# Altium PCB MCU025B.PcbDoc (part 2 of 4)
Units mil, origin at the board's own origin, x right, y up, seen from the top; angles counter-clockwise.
Board outline 2300 x 6150 mil, 6 copper layers (Top Signal, GND, Middle Signal, PWR, GND2, Bottom Signal), stack 61.64 mil thick; 237 components, 197 nets, 910 pads, 404 vias.
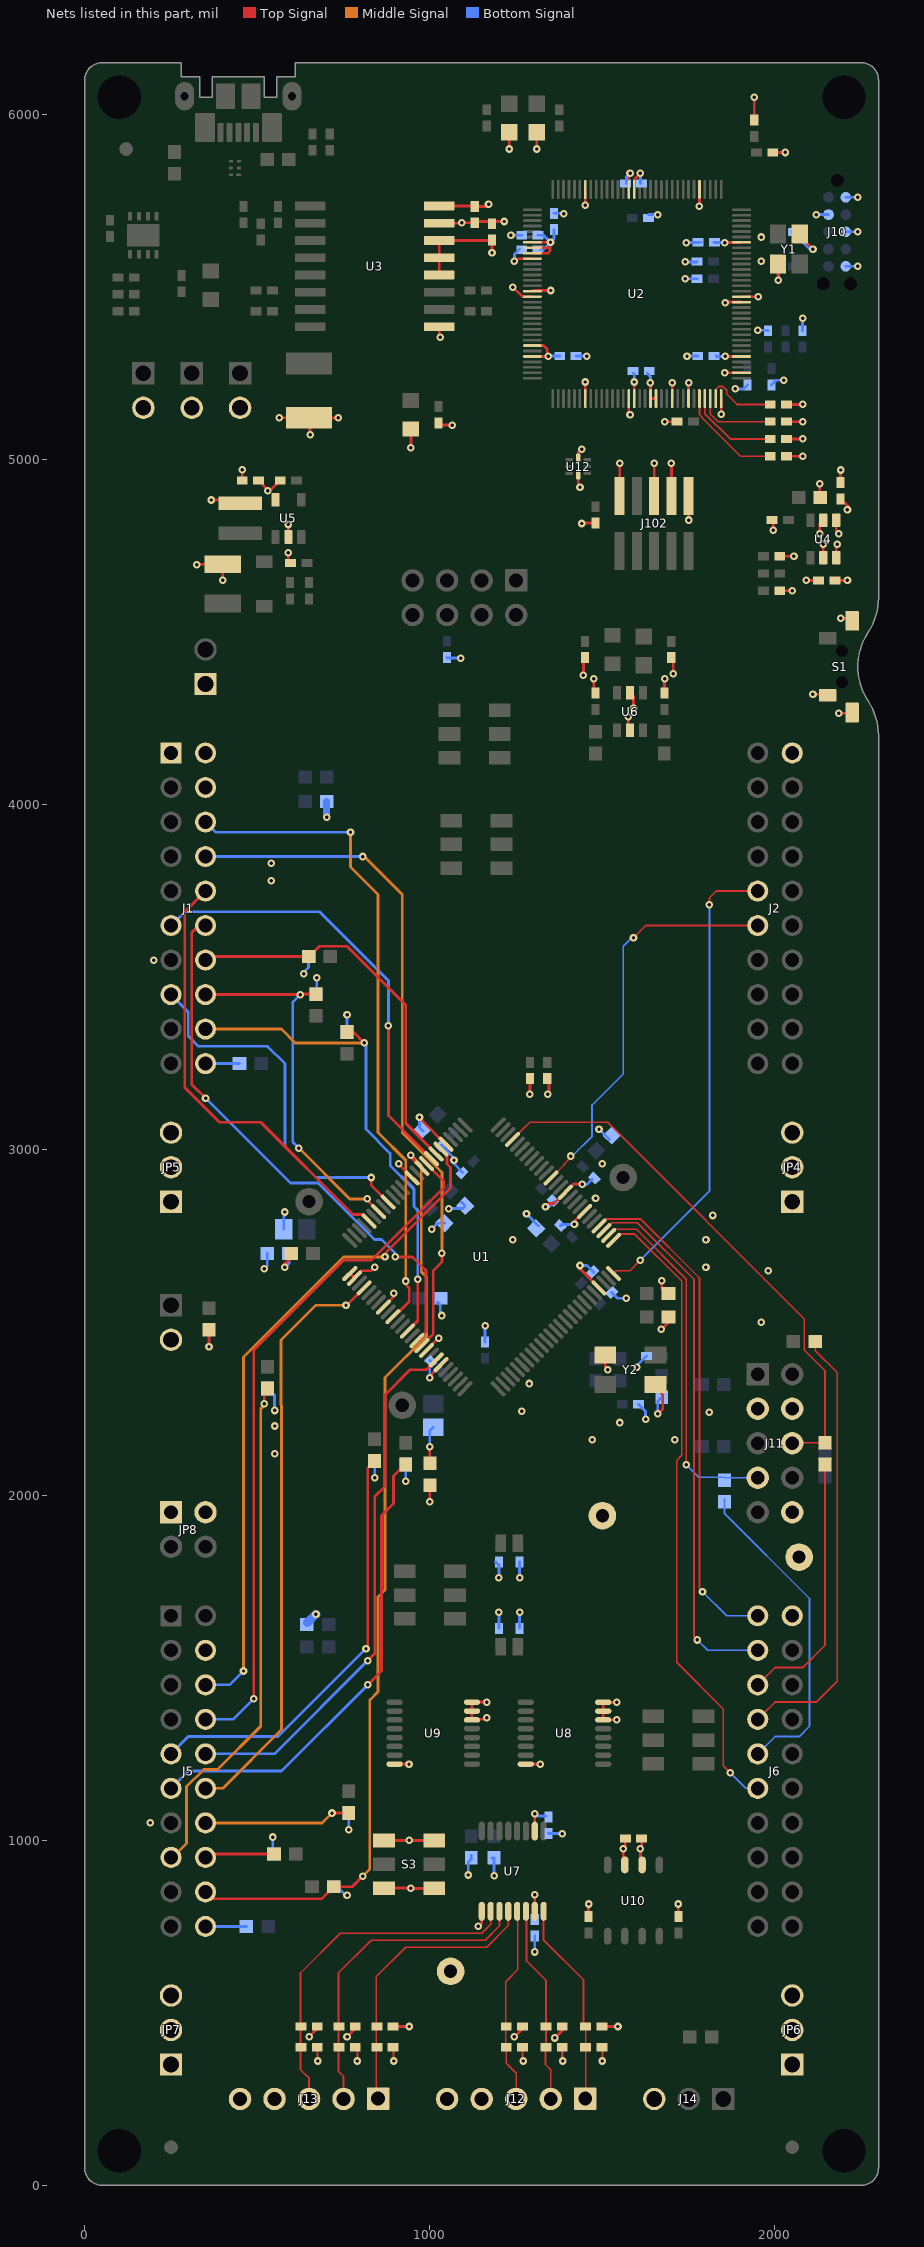
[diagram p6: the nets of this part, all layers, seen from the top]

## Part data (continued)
C3: library part CMP-0006493-2, "CAP, CERM, 820 pF, 50 V, +/- 5%, C0G/NP0, 0402", Cap_Case=0402, Manufacturer=MuRata, Supplier Part Number 1=490-3242-1-ND, TempCo=C0G/NP0, Tolerance_%=5%, Value1=Unknown, Value2=50V, ValueDisplayed=820pF
C4: library part CMP-0009190-2, "CAP, CERM, 10 uF, 25 V, +/- 10%, X7R, 1210", Cap_Case=1210, Manufacturer=MuRata, Supplier Part Number 1=490-1867-1-ND, TempCo=X7R, Tolerance_%=10%, Value1=Unknown, Value2=25V, ValueDisplayed=10uF
C5: library part CMP-0006552-2, "CAP, CERM, 4.7 uF, 6.3 V, +/- 20%, X5R, 0402", Cap_Case=0402, Manufacturer=MuRata, Supplier Part Number 1=490-5915-1-ND, TempCo=X5R, Tolerance_%=20%, Value1=Unknown, Value2=6.3V, ValueDisplayed=4.7uF
C7 C8 C50 C51 C52 C53 C58: library part CMP-0006658-2, "CAP, CERM, 0.01 uF, 25 V, +/- 10%, X7R, 0402", Cap_Case=0402, Manufacturer=MuRata, Supplier Part Number 1=490-1312-1-ND, TempCo=X7R, Tolerance_%=10%, Value1=Unknown, Value2=25V, ValueDisplayed=0.01uF
C9 C10 C19 C20: library part CMP-0007318-5, "CAP, CERM, 10 uF, 10 V, +/- 20%, X5R, 0603", Cap_Case=0603, Manufacturer=MuRata, TempCo=X5R, Tolerance_%=20%, Value1=Unknown, Value2=10V, ValueDisplayed=10uF
C15 C16 C17 C18 C35 C36: library part CMP-0007323-5, "CAP, CERM, 2.2 uF, 10 V, +/- 10%, X5R, 0603", Cap_Case=0603, Manufacturer=MuRata, Supplier Part Number 1=490-1545-1-ND, TempCo=X5R, Tolerance_%=10%, Value1=Unknown, Value2=10V, ValueDisplayed=2.2uF
C26 C27 C28 C29 C30 C31 C32 C33 C34: library part CMP-0007209-4, "CAP, CERM, 330 pF, 50 V, +/- 5%, C0G/NP0, 0603", Cap_Case=0603, Manufacturer=MuRata, Supplier Part Number 1=490-1439-1-ND, TempCo=C0G/NP0, Tolerance_%=5%, Value1=Unknown, Value2=50V, ValueDisplayed=330pF
C38 C39 C102: library part CMP-0006420-2, "CAP, CERM, 15 pF, 50 V, +/- 5%, C0G/NP0, 0402", Cap_Case=0402, Manufacturer=MuRata, Supplier Part Number 1=81-GRM1555C1H150JA1D, TempCo=C0G/NP0, Tolerance_%=5%, Value1=Unknown, Value2=50V, ValueDisplayed=15pF
C43 C44 C45 C46 C47 C48: library part CMP-0006673-2, "CAP, CERM, 1000 pF, 50 V, +/- 10%, X7R, 0402", Cap_Case=0402, Manufacturer=MuRata, Supplier Part Number 1=490-1303-1-ND, TempCo=X7R, Tolerance_%=10%, Value1=Unknown, Value2=50V, ValueDisplayed=1000pF
C54 C55 C60 C66: library part CMP-0006623-2, "CAP, CERM, 0.1 uF, 6.3 V, +/- 10%, X7R, 0402", Cap_Case=0402, Manufacturer=MuRata, Supplier Part Number 1=GRM155R70J104KA01D-ND, TempCo=X7R, Tolerance_%=10%, Value1=Unknown, Value2=6.3V, ValueDisplayed=0.1uF
C56 C57 C61: library part CMP-0006563-2, "CAP, CERM, 1 uF, 10 V, +/- 10%, X5R, 0402", Cap_Case=0402, Manufacturer=MuRata, Supplier Part Number 1=490-3890-1-ND, TempCo=X5R, Tolerance_%=10%, Value1=Unknown, Value2=10V, ValueDisplayed=1uF
C59 C100 C103: library part CMP-0006543-2, "CAP, CERM, 2.2 uF, 6.3 V, +/- 10%, X5R, 0402", Cap_Case=0402, Manufacturer=MuRata, Supplier Part Number 1=81-GRM155R60J225KE5D, TempCo=X5R, Tolerance_%=10%, Value1=Unknown, Value2=6.3V, ValueDisplayed=2.2uF
C62 C63: library part CMP-0006415-2, "CAP, CERM, 12 pF, 50 V, +/- 5%, C0G/NP0, 0402", Cap_Case=0402, Manufacturer=MuRata, Supplier Part Number 1=14T3292, TempCo=C0G/NP0, Tolerance_%=5%, Value1=Unknown, Value2=50V, ValueDisplayed=12pF
C101: library part CMP-0006688-2, "CAP, CERM, 3300 pF, 50 V, +/- 10%, X7R, 0402", Cap_Case=0402, Manufacturer=MuRata, Supplier Part Number 1=490-3248-1-ND, TempCo=X7R, Tolerance_%=10%, Value1=Unknown, Value2=50V, ValueDisplayed=3300pF
C104: library part CMP-0009297-2, "CAP, CERM, 0.01 uF, 1500 V, +/- 10%, X7R, 1812", Cap_Case=1812, Manufacturer=AVX, Supplier Part Number 1=478-4735-1-ND, TempCo=X7R, Tolerance_%=10%, Value1="0.05 ohm", Value2=1500V, ValueDisplayed=0.01uF
"CE Logo1": library part CMP-0074844-1
D1: library part CMP-0028360-1, "Diode, Schottky, 40 V, 1 A, SOD-123", Manufacturer="Diodes Inc.", Supplier Part Number 1=1N5819HW-FDICT-ND, Value1=1A, Value2=0.45V
FID1 FID2 FID3 FID4 FID5 FID6: library part CMP-0077181-1, "Fiducial mark.  There is nothing to buy or mount.", Manufacturer=N/A
J1 J5: library part CMP-0003837-2, "Receptacle, 2.54mm, 10x2, Tin, TH", Alternate Manufacturer="Major League Electronics", Alternate PartNumber=CRD-081413-A-G, Manufacturer=Samtec, Supplier Part Number 1=SAM1204-10-ND
J2 J6: library part CMP-0078266-2, "Receptacle, 2.54mm, 10x2, Tin, TH", Alternate Manufacturer="Major League Electronics", Alternate PartNumber=CRD-081413-A-G, Manufacturer=Samtec, Supplier Part Number 1=SAM1204-10-ND
J10: library part CMP-0075101-1, "Footprint for Tag-Connect TC2050 No-Legs cables", Manufacturer=Tag-Connect
J11: library part CMP-0075410-2, "Header, 100mil, 5x2, Gold, TH", Color=Black, Current_A=6.3A, Manufacturer=Samtec, Supplier Part Number 1=SAM1028-05-ND, Voltage_V=550V
J12 J13: library part CMP-0075411-1, "Header, 100mil, 5x1, Gold, TH", Color=Black, Current_A=6.3A, Manufacturer=Samtec, Supplier Part Number 1=SAM1029-05-ND, Voltage_V=550V
J14 JP4 JP5 JP6 JP7: library part CMP-0054796-1, "Header, 2.54 mm, 3x1, Gold, TH", Manufacturer="Wurth Elektronik", Supplier Part Number 1=732-5316-ND
J15 JP1 JP2 JP3 JP9: library part CMP-0054794-1, "Header, 2.54 mm, 2x1, Gold, TH", Manufacturer="Wurth Elektronik", Supplier Part Number 1=732-5315-ND
J101: library part CMP-0075408-1, "Header, 100mil, 4x2, Gold, TH", Color=Black, Current_A=6.3A, Manufacturer=Samtec, Supplier Part Number 1=SAM1028-04-ND, Voltage_V=550V
J102: library part CMP-0075670-1, "Header (Shrouded), 1.27mm, 5x2, Gold, SMT", Color=Black, Current_A=3.3A, Manufacturer=Samtec, Supplier Part Number 1=SAM8796-ND
JP8: library part CMP-0075404-1, "Header, 100mil, 2x2, Gold, TH", Color=Black, Current_A=6.3A, Manufacturer=Samtec, Supplier Part Number 1=SAM1028-02-ND, Voltage_V=550V
L1: library part CMP-0063754-1, "Inductor, Shielded Drum Core, Ferrite, 3.3 uH, 1.5 A, 0.085 ohm, SMD", Manufacturer="Wurth Elektronik", Supplier Part Number 1=732-2614-1-ND, Value1="0.085 ohm", Value2=1.5A, ValueDisplayed=3.3uH
L2: library part CMP-0003306-1, "Ferrite Bead, 60 ohm @ 100 MHz, 3 A, 0805", Manufacturer="Taiyo Yuden", Supplier Part Number 1=587-1932-1-ND, Value1="0.025 ohm", Value2=3A, ValueDisplayed="60 ohm"
L3: library part CMP-0003363-1, "Ferrite Bead, 220 ohm @ 100 MHz, 2 A, 0805", Manufacturer=MuRata, Supplier Part Number 1=490-1054-1-ND, Value1="0.045 ohm", Value2=2A, ValueDisplayed="220 ohm"
L100 L101: library part CMP-0003183-2, "Ferrite Bead, 100 ohm @ 100 MHz, 0.5 A, 0603", Manufacturer="Wurth Elektronik", Supplier Part Number 1=732-1579-1-ND, Value1="0.15 ohm", Value2=0.5A, ValueDisplayed="100 ohm"
LED0 LED1 LED4: library part CMP-0002951-2, "LED, Red, SMD", Color=Red, Manufacturer="Wurth Elektronik", Power_TotalModule=72mW, Supplier Part Number 1=732-4985-1-ND, Value1=0.072W, Value2=1.9V
LED2 LED3: library part CMP-0002889-1, "LED, Blue, SMD", Color=Blue, Manufacturer=Lite-On, Supplier Part Number 1=160-1579-1-ND, Value1=W, Value2=3.3V
LED5: library part CMP-0002830-2, "LED, Green, SMD", Color=green, Manufacturer=Lite-On, Supplier Part Number 1=160-1423-1-ND, Value1=W, Value2=2.1V
Logo1: library part CMP-0074838-1, "Texas Instrument Corporate Signature"
Logo2: library part CMP-0074769-1
Logo3: library part CMP-0074847-1, "FCC_disclaimer"
Logo4: library part CMP-0861049-2, "INSTASPIN FOC LOGO"
M1 M2 M3 M4 M5 M6 M7 M8 M9: library part CMP-0003761-2, "Shunt, 2.54mm, Gold, Black", Manufacturer="Wurth Elektronik", Supplier Part Number 1=732-2678-ND
MH1 MH2 MH3 MH4: library part CMP-0078424-2, "PCB Mounting Hole, No Pad", Manufacturer=Any, PartNumber=N/A
R1 R2 R103 R104: library part CMP-0026197-2, "RES, 24.3, 1%, 0.063 W, AEC-Q200 Grade 0, 0402", Manufacturer=Vishay-Dale, Power_W=63mW, Supplier Part Number 1=541-24.3LCT-ND, TempCo="100 ppm/C", Tolerance_%=1%, Value2=0.063W, Value_Code=24R3, ValueDisplayed=24.3
R3 R29 R30 R105: library part CMP-0026962-3, "RES, 680, 5%, 0.063 W, AEC-Q200 Grade 0, 0402", Manufacturer=Vishay-Dale, Power_W=63mW, Supplier Part Number 1=541-680JCT-ND, TempCo="200 ppm/C", Tolerance_%=5%, Value2=0.063W, Value_Code=680R, ValueDisplayed=680
R4 R10 R32 R40 R41: library part CMP-0026890-5, "RES, 2.2 k, 5%, 0.063 W, AEC-Q200 Grade 0, 0402", Manufacturer=Vishay-Dale, Power_W=63mW, Supplier Part Number 1=541-2.2KJCT-ND, TempCo="200 ppm/C", Tolerance_%=5%, Value2=0.063W, Value_Code=2k20, ValueDisplayed=2.2k
R5: library part CMP-0026822-3, "RES, 0, 5%, 0.063 W, AEC-Q200 Grade 0, 0402", Manufacturer=Vishay-Dale, Power_W=63mW, Supplier Part Number 1=541-0.0JCT-ND, TempCo="200 ppm/C", Tolerance_%=5%, Value2=0.063W, Value_Code=0000, ValueDisplayed=0
R6 R42: library part CMP-0025769-4, "RES, 2.2 k, 5%, 0.1 W, AEC-Q200 Grade 0, 0603", Manufacturer=Vishay-Dale, Power_W=100mW, Supplier Part Number 1=541-2.2KGCT-ND, TempCo="200 ppm/C", Tolerance_%=5%, Value2=0.1W, Value_Code=2k20, ValueDisplayed=2.2k
R7: library part CMP-0026730-1, "RES, 30.1 k, 1%, 0.063 W, 0402", Manufacturer="Yageo America", Power_W=63mW, Supplier Part Number 1=311-30.1KLRCT-ND, TempCo="100 ppm/C", Tolerance_%=1%, Value2=0.063W, Value_Code=30k1, ValueDisplayed=30.1k
R8 R9 R65 R67: library part CMP-0026825-5, "RES, 10 k, 5%, 0.063 W, AEC-Q200 Grade 0, 0402", Manufacturer=Vishay-Dale, Power_W=63mW, Supplier Part Number 1=541-10KJCT-ND, TempCo="200 ppm/C", Tolerance_%=5%, Value2=0.063W, Value_Code=10k0, ValueDisplayed=10k
R11 R12 R13 R14 R15 R16 R17 R18 R19 R20 R21 R22 R23 R24 R25 R26 R27 R28 R31 R35 R38 R39 R43 R44 R45 R46 R47 R71 R72: library part CMP-0025697-4, "RES, 0, 5%, 0.1 W, AEC-Q200 Grade 0, 0603", Manufacturer=Vishay-Dale, Power_W=100mW, Supplier Part Number 1=541-0.0GCT-ND, TempCo="200 ppm/C", Tolerance_%=5%, Value2=0.1W, Value_Code=0000, ValueDisplayed=0
R33 R34: library part CMP-0026949-3, "RES, 56 k, 5%, 0.063 W, AEC-Q200 Grade 0, 0402", Manufacturer=Vishay-Dale, Power_W=63mW, Supplier Part Number 1=541-56KJCT-ND, TempCo="200 ppm/C", Tolerance_%=5%, Value2=0.063W, Value_Code=56k0, ValueDisplayed=56k
R36 R37: library part CMP-0026826-2, "RES, 10 M, 5%, 0.063 W, AEC-Q200 Grade 0, 0402", Manufacturer=Vishay-Dale, Power_W=63mW, Supplier Part Number 1=541-10MJCT-ND, TempCo="200 ppm/C", Tolerance_%=5%, Value2=0.063W, Value_Code=10M0, ValueDisplayed=10M
R48 R49 R50 R51 R52 R53: library part CMP-0026071-3, "RES, 1.00 k, 1%, 0.063 W, AEC-Q200 Grade 0, 0402", Manufacturer=Vishay-Dale, Power_W=63mW, Supplier Part Number 1=541-1.00KLCT-ND, TempCo="100 ppm/C", Tolerance_%=1%, Value2=0.063W, Value_Code=1k00, ValueDisplayed=1.00k
R54 R56: library part CMP-0025958-3, "RES, 10.0 k, 1%, 0.063 W, AEC-Q200 Grade 0, 0402", Manufacturer=Vishay-Dale, Power_W=63mW, Supplier Part Number 1=541-10.0KLCT-ND, TempCo="100 ppm/C", Tolerance_%=1%, Value2=0.063W, Value_Code=10k0, ValueDisplayed=10.0k
R55: library part CMP-0022769-3, "RES, 120, 1%, 0.1 W, 0603", Manufacturer="Yageo America", Power_W=100mW, Supplier Part Number 1=311-120HRCT-ND, TempCo="200 ppm/C", Tolerance_%=1%, Value2=0.1W, Value_Code=120R, ValueDisplayed=120
R57: library part CMP-0026918-5, "RES, 3.3 k, 5%, 0.063 W, AEC-Q200 Grade 0, 0402", Manufacturer=Vishay-Dale, Power_W=63mW, Supplier Part Number 1=541-3.3KJCT-ND, TempCo="200 ppm/C", Tolerance_%=5%, Value2=0.063W, Value_Code=3k30, ValueDisplayed=3.3k
R58 R59 R60 R61: library part CMP-0026852-3, "RES, 1.0 k, 5%, 0.063 W, AEC-Q200 Grade 0, 0402", Manufacturer=Vishay-Dale, Power_W=63mW, Supplier Part Number 1=541-1.0KJCT-ND, TempCo="200 ppm/C", Tolerance_%=5%, Value2=0.063W, Value_Code=1k00, ValueDisplayed=1.0k
R62 R66: library part CMP-0026824-3, "RES, 100, 5%, 0.063 W, AEC-Q200 Grade 0, 0402", Manufacturer=Vishay-Dale, Power_W=63mW, Supplier Part Number 1=541-100JCT-ND, TempCo="200 ppm/C", Tolerance_%=5%, Value2=0.063W, Value_Code=100R, ValueDisplayed=100
R63 R64: library part CMP-0026699-1, "RES, 470, 1%, 0.1 W, AEC-Q200 Grade 0, 0402", Manufacturer=Panasonic, Power_W=100mW, Supplier Part Number 1=P470LCT-ND, TempCo="100 ppm/C", Tolerance_%=1%, Value2=0.1W, Value_Code=470R, ValueDisplayed=470
R68: library part CMP-0026413-2, "RES, 4.87 k, 1%, 0.063 W, AEC-Q200 Grade 0, 0402", Manufacturer=Vishay-Dale, Power_W=63mW, Supplier Part Number 1=541-4.87KLCT-ND, TempCo="100 ppm/C", Tolerance_%=1%, Value2=0.063W, Value_Code=4k87, ValueDisplayed=4.87k
R70: library part CMP-0026946-3, "RES, 51, 5%, 0.063 W, AEC-Q200 Grade 0, 0402", Manufacturer=Vishay-Dale, Power_W=63mW, Supplier Part Number 1=541-51JCT-ND, TempCo="200 ppm/C", Tolerance_%=5%, Value2=0.063W, Value_Code=51R0, ValueDisplayed=51
R100: library part CMP-0026100-2, "RES, 1.00 M, 1%, 0.063 W, AEC-Q200 Grade 0, 0402", Manufacturer=Vishay-Dale, Power_W=63mW, Supplier Part Number 1=541-1.00MLCT-ND, TempCo="100 ppm/C", Tolerance_%=1%, Value2=0.063W, Value_Code=1M00, ValueDisplayed=1.00M
R101: library part CMP-0088102-2, "RES Thick Film SMD 51kO 1% 1/16W 0402 100ppm/K", Manufacturer=Vishay, Power_W=63mW, Tolerance_%=1%, ValueDisplayed=51k
R102: library part CMP-0078244-2, "RES, 30.0 k, 1%, 0.063 W, AEC-Q200 Grade 0, 0402", Manufacturer=Vishay-Dale, Power_W=63mW, Supplier Part Number 1=541-30.0KLCT-ND, TempCo="100 ppm/C", Tolerance_%=1%, Value2=0.063W, Value_Code=30k0, ValueDisplayed=30.0k
S1: library part CMP-0002328-1, "Switch, SPST, 0.05 A, 12 VDC, SMD", CurrentRating_mA=50A, Manufacturer=Diptronics
S2: library part CMP-0002230-1, "Switch, SPST, 2 Pos, 25mA, 24VDC, SMD", CurrentRating_mA=25A, Manufacturer="CTS Electrocomponents", Supplier Part Number 1=CT2182LPST-ND
S3: library part CMP-0002233-1, "Switch, Dual SPDT,  2 Pos, 0.1A, 6VDC, SMD", CurrentRating_mA=100A, Manufacturer="Copal Electronics", Supplier Part Number 1=CASD20JCT-ND
S4 S6 S8 S9: library part CMP-0002123-2, "SLIDE SWITCH DPDT  .1A, SMT", CurrentRating_mA=100A, Manufacturer="Copal Electronics", Supplier Part Number 1=CAS220JCT-ND
TP1 TP2 TP3 TP4 TP5 TP6: library part CMP-0078143-2, "TEST POINT.  No entry in BOM.", Manufacturer=N/A
U1: library part CMP-0078352-1, "Piccolo Microcontroller, PZ0100A (LQFP-100)", Alternate Manufacturer="Texas Instruments"
U2: library part CMP-0077953-1, "MSP432E401YTPDT, PDT0128A (TQFP-128)", Alternate Manufacturer="Texas Instruments", Alternate PartNumber=MSP432E401YTPDTR
U3: library part CMP-0074604-2, "Full/Low Speed 2.5 kV USB Digital Isolator, SOIC-16", Manufacturer="Analog Devices", Supplier Part Number 1=ADUM3160BRWZ-ND
U4: library part CMP-0067340-2, "High-Accuracy, Fixed-Threshold OV/UV Monitor, DDC0006A (SOT-23-T-6)", Alternate Manufacturer="Texas Instruments", Alternate PartNumber=TPS3702CX33DDCT
U5: library part CMP-0066119-1, "SIMPLE SWITCHER 2.7V to 5.5V, 2.1A Step-Up Regulator in SOT-23, DBV0005A (SOT-23-5)", Alternate Manufacturer="Texas Instruments", Alternate PartNumber=LMR62421XMFE/NOPB
U6: library part CMP-0051789-2, "Dual Buffer/Driver with Open-Drain Output, DBV0006A, LARGE T&R", F @ Nom Voltage(Max)(Mhz)=150, Generic Part Number=SN74LVC2G07, ICC @ Nom Voltage(Max)(mA)=0.01, Manufacturer="Texas Instruments", Operating Temperature Range(C)="-40 to 125", Rating=Catalog, tpd @ Nom Voltage(Max)(ns)=8.6,4.4,3.7,2.9, Voltage(Nom)(V)=1.8,2.5,3.3,5
U7: library part CMP-0067443-1, "6-Bit Bidirectional Voltage-Level Translator with Auto Direction Sensing and +/-15-kV ESD Protect, PW0016A (TSSOP-16)", Alternate Manufacturer="Texas Instruments"
U8 U9: library part CMP-0076549-1, "TRIPLE 2-CHANNEL ANALOG MULTIPLEXER/DEMULTIPLEXER, PW0016A (TSSOP-16)", Alternate Manufacturer="Texas Instruments"
U10: library part CMP-0033355-1, "3.3V CAN Transceiver with Sleep Mode, 6 mA, -40 to 125 degC, 8-pin SOIC (D), Green (RoHS & no Sb/Br)", Bus Fault Voltage(V)=+/-30, Drivers Per Package=1, Low Power Mode=Sleep, Manufacturer="Texas Instruments", Rating=Catalog, Supply Voltage(s)(V)=3.3
U12: library part CMP-0043125-2, "Low-Capacitance + / - 15 kV ESD Protection Array for High-Speed Data Interfaces, 6 Channels, -40 to +85 degC, 8-pin UQFN (RSE), Green (RoHS & no Sb/Br)", Breakdown Voltage(Min)(V)=6, IO Capacitance(Typ)(pF)=1.6, IO Leakage Current(nA)=1, Manufacturer="Texas Instruments"
U100: library part CMP-0043115-2, "ESD-Protection Array for High-Speed Data Interfaces, 4 Channels, -40 to +85 degC, 6-pin SON (DRY), Green (RoHS & no Sb/Br)", Breakdown Voltage(Min)(V)=6, IO Capacitance(Typ)(pF)=1.6, IO Leakage Current(nA)=1, Manufacturer="Texas Instruments"
U101: library part CMP-0036402-3, "Single Output High PSRR LDO, 1 A, Adjustable 1.2 to 5.5 V Output, 2.7 to 5.5 V Input, 8-pin SON (DRB), -40 to 125 degC, Green (RoHS & no Sb/Br)", Manufacturer="Texas Instruments"
USB101: library part CMP-0055311-1, "Receptacle, USB 2.0, Micro B, 5 Position, R/A, SMT", Color=Black, Current_A=1.8A, Manufacturer=Molex, Supplier Part Number 1=WM11263CT-ND, Voltage_V=30V
Y1: library part CMP-0004635-3, "Crystal, 16 MHz, 8pF, SMD", Frequency_Fixed=16MHz, Frequency Stability=+/-30ppm, Manufacturer=NDK, Supplier Part Number 1=644-1157-1-ND
Y2: library part CMP-0080365-1, "Crystal, 20 MHz, 25 ppm, 18, SMD", Frequency_Fixed=20MHz, Frequency Stability="30 ppm", Frequency Tolerance="25 ppm", Load Capacitance=18, Manufacturer="ECS Inc.", Supplier Part Number 1=XC2693CT-ND
ZZ2: library part CMP-0077236-1
ZZ3: library part CMP-0077237-1
ZZ4: library part CMP-0077238-1

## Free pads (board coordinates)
  round 0 on Mech16 paste+0 mask+0: 1(496.18,5248.19) 1(496.18,5248.19)
  rrect9% 41.73x57.87 on Top Paste: 9(145.2,5650) 9(194.8,5650)

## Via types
v1: diameter 22, hole 10, Top Signal to Bottom Signal, tented both sides, 400 vias
v2: diameter 19.68, hole 7.87, Top Signal to Bottom Signal, 4 vias

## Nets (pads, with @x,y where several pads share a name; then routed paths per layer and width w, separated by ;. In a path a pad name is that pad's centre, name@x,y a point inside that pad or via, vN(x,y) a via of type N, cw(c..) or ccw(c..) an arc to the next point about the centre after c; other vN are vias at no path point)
+3V3: C1.2 C2.2 C5.1 C6.2 C15.1 C19.1 C40.2 C41.1 C49.2 C51.1 C52.1 C53.1 C54.1 C55.1 C56.1 C57.1 C58.1 J1.1 J10.1 J11.10 J102.1 JP2.2 JP4.1 JP6.1 JP8.1 L1.1 L2.1 L3.1 R3.2 R4.2 R6.2 R8.2 R10.2 R11.2 R29.2 R30.2 R32.2 R33.2 R34.2 R36.2 R37.2 R42.1 R54.2 R57.2 R58.2 R59.2 R60.2 R61.2 R65.2 R70.2 S3.3 S3.6 TP4.1 U2.7 U2.8 U2.9 U2.16 U2.26 U2.28 U2.39 U2.47 U2.51 U2.52 U2.69 U2.79 U2.90 U2.101 U2.113 U2.122 U3.12 U3.13 U3.14 U3.16 U4.3 U4.4 U4.5 U5.5 U6.5 U7.2 U8.16 U9.16 U10.3 U12.8 | length 3634.6
  Top Signal w8: v1(366,4883) 440.31,4883 L1.1@450,4873.31 ; C5.1@500,4940 C5.1@503.62,4940 v1@530,4913.62 ; v1(530,4910) 536.38,4910 R8.2@566.38,4940 R8.2@570,4940 ; S3.6@867.17,998.9 938.9,998.9 v1(940,1000) 941.1,998.9 S3.3@1012.83,998.9 ; U9.16@897.8,1220.43 v1(939.57,1220.43) ; C19.1@1000,2090 C19.1@1000.75,2090.75 ; C19.1@1000,2091.5 v1(1000,2140) ; R3.2@1025,5105 1030,5100 v1(1065,5100) ; U3.12@1027.01,5535 1027.01,5627.01 U3.14@1030,5630 ; U3.16@1027.01,5735 C1.2@1135,5735 ; U3.14@1030,5640 1030,5635 C2.2@1175,5635 ; C1.2@1140,5733.62 1163.62,5733.62 v1(1170,5740) ; v1(1180,5600) C2.2@1180,5636.38 ; U8.16@1277.8,1220.43 v1(1319.57,1220.43) ; U2.28@1296.85,5298.9 1296.95,5299 v1(1343,5299) ; U2.26@1296.85,5330.39 1329.61,5330.39 1340,5320 v1@1340,5300 ; U2.16@1296.85,5487.87 1298.98,5490 v1(1350,5490) ; U2.9@1296.85,5598.11 1341.75,5598.11 1347.86,5604.22 1347.86,5613.86 ; U2.8@1296.85,5613.86 1347.86,5613.86 ; U2.7@1296.85,5629.61 1349,5629.61 1349,5615 1347.86,5613.86 ; U7.2@1303.98,1026.14 1303,1027.12 1304,1028.12 v1(1304,1076) ; R32.2@1340,3206.38 1345,3201.38 v1@1345,3160 ; U12.8@1430,4954.41 1430,4925 v1(1435,4920) ; v1(1440,4815) 1441.38,4816.38 R57.2@1480,4816.38 ; v1@1449.37,4375.63 1448.74,4375 v1(1445,4375) 1445,4420 R29.2@1450,4425 ; v1(1450,5225) 1450,5177.24 U2.39@1450.39,5176.85 ; v1(1450,5737) 1450,5782.76 U2.122@1450.39,5783.15 ; R54.2@1460,778.62 v1(1460,815) ; v1(1475,4365) 1475,4340 1480,4335 R36.2@1480,4323.62 R36.2@1479.31,4324.31 ; v1(1560,975) 1560,933.35 U10.3@1565,928.35 ; v1@1566.38,978.62 C49.2@1566.38,1005 ; U2.47@1576.38,5176.85 1576.38,5133.62 v1(1580,5130) ; U6.5@1580,4324.13 1590,4314.13 v1(1590,4280) ; U2.113@1592.13,5783.15 1592.13,5812.13 v1(1610,5830) ; v1(1639,5223) 1639,5219.74 1639.37,5219.37 1639.37,5176.85 U2.52@1654.78,5176.85 ; v1(1672,2621) 1672,2598 1690,2580 R11.2@1691.5,2580 ; R37.2@1680,4323.62 v1(1680,4365) ; R30.2@1699.37,4426.22 1705,4420.59 v1(1705,4380) ; v1(1750,4825) J102.1@1750,4895.12 ; v1(1781,5734) 1781,5783.05 U2.101@1781.1,5783.15 ; v1(1854,5629) 1901.76,5629 1902.76,5630 U2.90@1903.15,5629.61 ; v1@1855,5455 1856.38,5456.38 U2.79@1903.15,5456.38 ; v1(1856,5299) 1861,5299 1861.1,5298.9 U2.69@1903.15,5298.9 ; R4.2@2013.62,4720 v1(2055,4720) ; R61.2@2033.62,5010 v1(2080,5010) ; R60.2@2033.62,5060 v1(2080,5060) ; R59.2@2033.62,5110 v1(2080,5110) ; R58.2@2033.62,5160 v1(2080,5160) ; v1(2130,4785) 2130,4814.13 U4.5@2140,4824.13 ; R6.2@2130,4888 v1(2130,4930) ; C6.2@2173.62,4650 v1(2210,4650) ; U4.3@2177.4,4715.87 2177.4,4747.4 2177,4747.8 2180,4750.8 v1(2180,4755) ; U4.4@2177.4,4824.13 2177.4,4792.6 v1(2185,4785) ; C40.2@2190,4886.38 2213,4863.38 2210,4860.38 v1(2210,4855)
  Bottom Signal w8: v1(520,2655) 528.51,2663.51 C15.1@528.5,2700 ; L2.1@576.54,2770 576.54,2806.54 580,2810 v1(580,2820) ; v1(1000,2140) 1000,2186.54 L3.1@1010,2196.54 ; R10.2@1050,4426.38 1051.38,4425 v1(1090,4425) ; v1(1111,899) 1111,935.5 1121,945.5 1119,947.5 R42.1@1120,948.5 R42.1@1120,956.38 ; R33.2@1190,1806.38 1200,1796.38 v1(1200,1760) ; v1(1260,1760) R34.2@1260,1806.38 ; v1@1310,1070 C41.1@1336.38,1070 ; C58.1@1313.62,5650 1330,5650 1350,5630 1360,5640 C56.1@1360,5666.38 ; C57.1@1320,5610 1330,5610 v1(1349.61,5629.61) ; v1@1340,5300 C55.1@1376.38,5300 ; C51.1@1610,5800 v1(1610,5830) ; C54.1@1630,5250 1640,5240 1639,5239 v1(1639,5223) ; C52.1@1823,5630 1824,5629 v1(1854,5629) 1859,5629 1860,5630 v1@1854,5630 ; C53.1@1830,5300 1831,5299 v1(1856,5299) ; v1(1885,5205) 1908.62,5205 R70.2@1920,5216.38 ; v1(1950,5375) 1978.62,5375 R65.2@1980,5373.62 ; J10.1@2205,5760 v1(2240,5760)
  other v1: 1342,3161 1856,5455
+5V0: C42.2 J1.21 J12.4 J13.4 JP3.2 JP5.1 JP7.1 JP8.2 JP9.1 R48.2 R49.2 R50.2 R51.2 R52.2 R53.2 R62.1 TP5.1 U7.15 | length 384
  Top Signal w6: v1(675,360) R53.2@675,400 ; R52.2@785,400 790,395 v1(790,360) ; v1(895,360) R51.2@895,400 ; R50.2@1268.62,400 1268.62,361.38 v1(1270,360) ; U7.15@1304,785.88 v1(1304,842) ; U7.15@1303.98,793.86 1300,789.88 U7.15@1305,784.88 ; R49.2@1383.62,400 1383.62,361.38 v1(1385,360) ; R48.2@1493.62,400 R48.2@1498.62,400 1500,398.62 v1(1500,360) ; R62.1@1940,5983.62 v1(1940,6050)
ADCINA0: J5.30 R13.1 | length 118.5
  Bottom Signal w8: J5.30@350,750 R13.1@468.5,750
ADCINA1: J1.30 R15.1 | length 108.5
  Bottom Signal w8: J1.30@340,3250 J1.30@350,3250 R15.1@448.5,3250
ADCINA2: J5.24 U1.9 | length 2010.7
  Top Signal w8: v1(490,1410) 490,2420 750,2680 830,2680 1040,2890 1040,2910 990.62,2959.38 U1.9@990.62,2960.73
  Bottom Signal w8: J5.24@350,1350 430,1350 v1(490,1410)
ADCINA3_P2I: J5.29 R16.2 U1.10 | length 2765.7
  Top Signal w8: J5.29@350,850 370,830 686.5,830 R16.2@721.5,865 775,865 v1(805,895) ; 790,880 v1(805,895) ; 792.5,882.5 v1(805,895) ; v1(945,2985) 945,2978.52 U1.10@976.7,2946.81
  Middle Signal w8: v1(805,895) 826,916 826,1406 850,1430 850,1705 870,1725 870,2340 990,2460 990,2631.87 975,2646.87 975,2955 v1(945,2985)
ADCINA4_P2OF: J5.6 R19.1 | length 1379.8
  Top Signal w8: v1(820,1450) 860,1490 860,1940 895,1975 895,2055 R19.1@930,2090
  Bottom Signal w8: J5.6@250,1150 300,1200 570,1200 v1(820,1450)
ADCINA5: J1.23 U1.35 | length 1927.6
  Top Signal w8: U1.35@893.19,2516.7 896.7,2516.7 940,2560 940,2600 930,2610 v1(930,2620)
  Middle Signal w8: v1(770,3920) 770,3820 850,3740 850,3050 930,2970 v1(930,2620)
  Bottom Signal w8: J1.23@350,3950 380,3920 760,3920 v1(770,3920)
ADCINA6: J5.23 U1.6 | length 1969.4
  Top Signal w8: v1(870,2690) 870,2700 1060,2890 1060,2949 1049.37,2959.63 1049.37,2985.63 1032.51,3002.49 U1.6@1032.38,3002.49
  Middle Signal w8: v1(460,1490) 460,2400 750,2690 v1(870,2690)
  Bottom Signal w8: J5.23@350,1450 420,1450 v1(460,1490)
ADCINA8_P6OF: J5.8 R22.1 | length 1499.4
  Top Signal w8: v1(520,2265) 520,2295 R22.1@530,2305
  Middle Signal w8: J5.8@250,945 295,990 295,1155 345,1205 385,1205 510,1330 510,2250 520,2260 v1(520,2265)
ADCINA9_P5I: J1.29 R20.2 U1.38 | length 1483.8
  Top Signal w8: J1.29@350,3350 J1.29@360,3340 ; R20.2@760,3341.5 778.5,3341.5 v1(810,3310) ; U1.38@934.94,2474.94 965,2505 v1(965,2625)
  Middle Signal w8: J1.29@345,3350 J1.29@350,3350 570,3350 610,3310 v1(810,3310)
  Bottom Signal w8: v1(810,3310) 815,3305 815,3060 885,2990 885,2955 954,2886 954,2836 965,2825 965,2628.42 959,2622.42 v1@959,2622.13 ; v1@958.43,2621.56 961.87,2625 v1(965,2625)
ADCINB0: J1.24 U1.41 | length 1994.2
  Top Signal w8: U1.41@976.7,2433.19 1001,2457.48 1001,2457.87 1010,2466.87 1010,2650 1035,2675 v1(1035,2700)
  Middle Signal w8: v1(805,3850) 810,3850 920,3740 920,3050 1035,2935 v1(1035,2700)
  Bottom Signal w8: J1.24@350,3850 v1(805,3850)
ADCINB1: J1.26 U1.40 | length 1619.4
  Top Signal w8: v1(350,3150) 310,3190 310,3630 J1.26@350,3670 ; v1(900,2690) 950,2690 989,2651 989,2473.32 U1.40@962.78,2447.11
  Bottom Signal w8: v1(350,3150) 596,2904 676,2904 840,2740 860,2740 900,2700 v1(900,2690)
ADCINB2_P1I: J1.27 R14.2 U1.7 | length 1133.6
  Top Signal w8: J1.27@350,3550 360,3560 R14.2@648.5,3560 ; R14.2@650,3560 680,3590 760,3590 930,3420 930,3077.03 U1.7@1018.46,2988.57
ADCINB3: J1.6 U1.8 | length 1296.3
  Top Signal w8: v1(880,3360) 880,3099.2 U1.8@1004.54,2974.65
  Bottom Signal w8: J1.6@250,3650 290,3690 680,3690 880,3490 v1(880,3360)
ADCINB4_P4OF: J5.5 R25.1 | length 1246.7
  Top Signal w8: v1(815,1555) 820,1560 820,2078.5 R25.1@840,2098.5 R25.1@841.5,2098.5
  Bottom Signal w8: J5.5@250,1250 300,1300 560,1300 v1(815,1555)
ADCINC0_P3I: J1.28 R17.2 U1.19 | length 1093.4
  Top Signal w8: J1.28@350,3450 v1(624,3450) 627.01,3450 628.5,3451.5 R17.2@670,3451.5 ; v1@817.97,2855 U1.19@851.43,2821.54 ; v1@818,2855.03 v1(818,2858)
  Middle Signal w8: v1(620,3005) 620.93,3005 767.97,2857.97 ; 768,2858 816,2858 818,2856 v1(818,2858)
  Bottom Signal w8: v1(620,3005) 603,3022 603,3429 v1(624,3450)
ADCINC1: J5.26 U1.29 | length 1723.1
  Top Signal w8: v1(757,2550) 759.45,2550 U1.29@809.67,2600.22
  Middle Signal w8: J5.26@350,1150 400,1150 570,1320 570,2261.13 569,2262.13 569,2449 670,2550 v1(757,2550)
ADCINC2: J1.25 U1.21 | length 1290.7
  Top Signal w8: J1.25@350,3750 290,3690 290,3180 390,3080 510,3080 777,2813 807,2813 U1.21@826,2794
ADCINC3_P4I: J5.27 R18.2 | length 428.9
  Top Signal w8: v1(716.5,1078.5) R18.2@765,1078.5
  Middle Signal w8: J5.27@350,1050 687.99,1050 v1(716.5,1078.5) v1@715,1080
ADCINC4: J1.8 U1.17 | length 1072.2
  Top Signal w8: v1(830,2920) 830,2898.65 U1.17@879.27,2849.38
  Bottom Signal w8: J1.8@250,3450 300,3400 300,3330 330,3300 530,3300 580,3250 580,3010 670,2920 v1(830,2920)
ADCINC5_P6I: J5.28 R21.2 | length 202.6
  Top Signal w8: J5.28@350,950 360,960 R21.2@548.5,960
ADCINC14: J5.25 U1.44 | length 1539.2
  Top Signal w8: v1(820,1520) 840,1540 840,1995 870,2025 870,2290 943,2363 990,2363 999.52,2372.52 U1.44@1002.52,2372.52
  Bottom Signal w8: J5.25@350,1250 550,1250 v1(820,1520)
DEBUG_ID4: R58.1 U2.63 | length 214.5
  Top Signal w5: U2.63@1828.35,5176.85 1828.35,5203.35 1836.91,5211.91 1848.83,5211.91 1860,5200.74 1860,5190 1890,5160 R58.1@1985,5160
DEBUG_ID5: R59.1 U2.62 | length 226.1
  Top Signal w5: U2.62@1812.6,5176.85 1812.6,5132.4 1835,5110 R59.1@1985,5110
DEBUG_ID6: R60.1 U2.61 | length 262.1
  Top Signal w5: U2.61@1796.85,5176.85 1796.85,5133.15 1870,5060 R60.1@1985,5060
DEBUG_ID7: R61.1 U2.60 | length 301.1
  Top Signal w5: U2.60@1781.1,5176.85 1781.1,5130.69 1786.87,5124.92 1786.87,5123.13 1900,5010 R61.1@1985,5010
EQEP1A: C43.1 J12.1 R48.1 U7.16 | length 600.5
  Top Signal w5: U7.16@1329.57,793.86 1329.57,710.43 1445,595 1445,465 1451.38,458.62 R48.1@1451.38,400 J12.1@1451.38,246.38 ; R48.1@1446.38,403.62 R48.1@1447.5,402.5 ; J12.1@1450,250 J12.1@1450,251
EQEP1B: C44.1 J12.2 R49.1 U7.14 | length 574
  Top Signal w5: U7.14@1278.39,790 U7.14@1278.39,793.86 ; U7.14@1280,790 1280,650 1336.38,593.62 C44.1@1336.38,460 1336.38,401.38 1335,400 1335,350 1350,335 J12.2@1350,250
EQEP1I: C45.1 J12.3 R50.1 U7.13 | length 573.4
  Top Signal w5: R50.1@1220,400 1220,590 1255,625 1255,790 U7.13@1250,795 ; R50.1@1221.38,400 1221.38,353.62 1250,325 J12.3@1250,250
EQEP2A: C46.1 J13.1 R51.1 U7.12 | length 848.6
  Top Signal w5: R51.1@846.38,400 R51.1@850,396.38 ; C46.1@846.38,460 C46.1@845,461.38 ; J13.1@850,250 845,255 C46.1@845,461.38 ; U7.12@1227.2,793.86 1227.2,752.8 1164.41,690 930,690 845,605 C46.1@845,461.38
EQEP2B: C47.1 J13.2 R52.1 U7.11 | length 938.6
  Top Signal w5: C47.1@736.38,458.62 C47.1@735,460 ; J13.2@750,250 750,315 735,330 C47.1@735,460 ; U7.11@1201.61,793.86 1201.61,751.61 1160,710 830,710 735,615 C47.1@735,460
EQEP2I: C48.1 J13.3 R53.1 U7.10 | length 1024.6
  Top Signal w5: C48.1@626.38,458.62 C48.1@625,460 ; J13.3@650,250 650,310 625,335 C48.1@625,460 ; U7.10@1176.02,793.86 1176.02,756.02 1150,730 740,730 625,615 C48.1@625,460
GND: C1.1 C2.1 C4.2 C5.2 C6.1 C7.2 C8.2 C9.1 C10.1 C11.2 C12.2 C13.2 C14.2 C15.2 C16.2 C17.2 C18.2 C19.2 C20.2 C21.1 C22.1 C23.1 C24.1 C25.1 C26.1 C27.1 C28.1 C29.1 C30.1 C31.1 C32.2 C33.2 C34.2 C35.2 C36.2 C37.1 C38.2 C39.2 C40.1 C41.2 C42.1 C43.2 C44.2 C45.2 C46.2 C47.2 C48.2 C49.1 C50.2 C51.2 C52.2 C53.2 C54.2 C55.2 C56.2 C57.2 C58.2 C59.2 C60.2 C61.2 C62.2 C63.2 C66.2 C104.1 J1.22 J2.20 J5.22 J6.20 J10.3 J10.5 J10.9 J11.3 J11.4 J12.5 J13.5 J14.3 J15.2 J102.3 J102.5 J102.9 JP1.2 JP4.2 JP4.3 JP5.2 JP5.3 JP6.2 JP6.3 JP7.2 JP7.3 LED1.1 LED2.2 LED3.2 R9.1 R12.2 R26.1 R27.1 R35.2 R40.1 R41.1 R43.1 R56.1 R67.1 R68.1 S1.1 S1.2 S1.3 S3.1 S3.4 TP6.1 U1.5 U1.12 U1.26 U1.27 U1.33 U1.42 U1.45 U1.72 U1.82 U1.86 U2.10 U2.17 U2.48 U2.55 U2.58 U2.64 U2.66 U2.80 U2.114 U3.9 U3.15 U4.2 U5.2 U6.2 U7.9 U8.6 U8.7 U8.8 U9.6 U9.7 U9.8 U10.2 U12.4 Y1.2 Y1.4 Y2.2 Y2.4 | length 6418.7
  Top Signal w8: v1(325,4695) 330.83,4695 332.91,4697.09 C4.2@400,4697.09 410,4687.09 400,4677.09 v1(400,4650) ; v1(360,2430) C35.2@360,2478.5 ; v1(456,4971) 456,4964 456.38,4963.62 C5.2@456.38,4940 ; v1(564,5121) 571,5121 571.26,5121.26 C104.1@650,5121.26 ; v1(580,2660) 580,2670 598.5,2688.5 C36.2@598.5,2700 ; v1(590,4730) 590,4705 R9.1@595,4700 ; U5.2@590,4775.87 v1(590,4812) ; v1(650,430) 675,455 C48.2@675,460 ; v1(653,5072) 653,5118.26 C104.1@650,5121.26 ; v1(734,5121) 652.26,5121 651.26,5120 C104.1@650,5121.26 ; v1(760,430) 785,455 C47.2@785,460 ; U1.26@770,2639.89 U1.27@781.83,2628.06 ; U1.27@780,2630 800,2650 830,2650 v1(840,2660) ; U1.33@865.35,2544.54 875.4,2554.6 U1.33@875.81,2555 ; S3.4@867.17,861.1 943.9,861.1 v1(945,860) S3.1@1015,860 ; U1.33@875,2555 U1.33@875.81,2555 ; C46.2@893.62,460 v1(940,460) ; v1(895,2585) 895,2574 876,2555 U1.33@875.81,2555 ; v1(910,2960) 910,2957.84 U1.12@948.86,2918.97 ; v1(945,5035) LED1.1@945,5088.66 ; v1(970,3095) 970,3092 1015,3047 1015,3046.72 1026.72,3035 1027.71,3035 U1.5@1046.3,3016.41 ; U1.42@990.62,2419.27 990.62,2420.62 1024,2454 v1(1026,2454) ; v1(1000,1980) C19.2@1000,2028.5 ; v1(1000,2340) 1000,2345.13 U1.45@1032.38,2377.51 ; v1@1027.01,5362.99 U3.9@1027.01,5385 ; U3.15@1027.01,5685 1090,5685 1091.38,5686.38 C1.1@1128.38,5686.38 ; U9.8@1122.2,1397.8 U9.7@1122.2,1373.98 U9.6@1122.2,1348.39 1123.82,1350 1160,1350 v1(1165,1355) ; U9.8@1122.2,1399.57 1122.64,1400 v1(1165,1400) ; C1.1@1125,5690 v1(1215,5690) ; C1.1@1130,5686.38 C1.1@1128.38,5686.38 ; C1.1@1130,5688 C1.1@1128.38,5686.38 ; v1(1140,750) 1150.43,760.43 U7.9@1150.43,793.86 ; v1(1230,5900) LED2.2@1230,5948.66 ; v1(1240,5500) 1267.87,5472.13 U2.17@1296.85,5472.13 ; v1(1245,430) 1270,455 C45.2@1270,460 ; v1(1245,5575) 1252.36,5582.36 U2.10@1296.85,5582.36 ; v1@1290,3160 C37.1@1290,3206.38 ; v1(1310,5900) LED3.2@1310,5948.66 ; v1(1335,2835) 1345,2845 1360,2845 1392.22,2877.22 U1.86@1392.89,2877.22 1416.68,2901 v1@1443,2901 ; v1@1360,422.76 v1@1361.96,424.72 ; v1@1360,426.38 v1@1360.43,426.81 ; v1@1361.2,427.57 v1@1360.43,426.81 ; v1@1367.24,430 v1@1362.24,425 ; C44.2@1385,460 1385,449.85 v1(1361.96,426.81) v1@1361.96,425.28 ; v1(1419,2784) 1419,2794 1447,2822 U1.82@1450,2822 ; U12.4@1430,5005.59 1430,5020 v1@1438.07,5028.07 ; v1(1435,2665) 1435,2655.55 U1.72@1490.33,2600.22 ; C43.2@1495,460 C43.2@1498.62,460 v1(1545,460) ; U8.8@1502.2,1397.8 U8.7@1502.2,1373.98 U8.6@1502.2,1348.39 1502.59,1348 1503.59,1349 v1(1541,1349) ; U8.8@1502.2,1399.57 1502.77,1399 v1(1541,1399) ; Y2.4@1508.38,2406.24 1508.38,2371.62 1516,2364 v1(1516,2363) ; J102.9@1550,4895.12 v1(1550,4990) ; v1(1575,4255) 1575,4220 U6.2@1580,4215 ; U2.114@1576.38,5783.15 1576.38,5826.38 v1(1580,5830) ; v1(1592,5225) 1592,5218 1592.13,5217.87 U2.48@1592.13,5176.85 ; v1(1610,975) 1610,933.35 U10.2@1615,928.35 ; v1@1613.62,978.62 C49.1@1613.62,1005 ; J102.5@1650,4895.12 v1(1650,4990) ; Y2.2@1654.05,2319.62 1654.05,2310.95 1675,2290 1675,2250 v1(1660,2235) ; v1(1670,2480) 1671,2480 1693,2502 1690,2505 R12.2@1690,2520 ; v1(1680,5110) R68.1@1716.38,5110 ; J102.3@1700,4895.12 v1(1700,4990) ; v1@1700,5225 v1(1702,5223) 1702.36,5222.64 U2.55@1702.36,5176.85 ; R56.1@1720,775 R56.1@1720,778.62 v1(1720,815) ; U2.58@1749.61,5176.85 1749.61,5224.61 v1@1750,5225 ; v1(1844,5131) 1844,5140.81 1844.09,5140.91 U2.64@1844.09,5176.85 ; v1@1851.65,5251.65 v1@1855,5251.65 ; v1@1855,5250 1856.65,5251.65 U2.66@1903.15,5251.65 ; v1(1855,5252) v1@1861.31,5252 ; U2.80@1903.15,5472.13 1947.87,5472.13 v1@1950,5470 ; v1@1950,5472 v1(1951,5472) ; C8.2@1991.38,4825 1995,4821.38 v1(1995,4795) ; C50.2@1993.62,5890 v1(2030,5890) ; Y1.4@2008.5,5566.69 2008.5,5531.5 2010,5530 v1(2010,5520) ; C7.2@2013.62,4620 v1(2050,4620) ; Y1.2@2070,5650 v1(2110,5610) ; v1(2090,4650) C6.1@2126.38,4650 ; v1(2110,4320) 2150,4320 S1.3@2150,4310 ; U4.2@2140,4715.87 v1(2140,4755) ; v1(2185,4265) S1.1@2225,4265 ; v1(2190,4540) 2216.18,4540 S1.2@2223.31,4532.87 ; C40.1@2190,4933.62 v1(2190,4970) ; v1@1360.43,426.81 v1@1361.96,425.28 ; v1@1361.96,424.72 v1@1361.96,425.28 ; v1@1361.96,424.72 v1@1362.24,425 ; v1@1361.96,425.28 v1@1362.24,425
  Bottom Signal w8: C33.2@530,2310 550,2290 v1(550,2245) ; v1(545,1009) 545,963.5 C31.1@550,958.5 ; v1(580,2660) 591.5,2671.5 C15.2@591.5,2700 ; v1(635,3510) 635,3515 648.5,3528.5 C26.1@648.5,3560 ; R27.1@643.5,1625 R27.1@643.5,1630 ; C28.1@670,3451.5 672,3453.5 v1(672,3499) ; R26.1@700,4010 R26.1@701,4009 ; C27.1@721.5,865 726.5,870 756.5,840 v1(760,840) ; C30.1@760,3341.5 v1(760,3392) ; v1(765,1030) C29.1@765,1078.5 C29.1@766.5,1080 ; v1(840,2050) C34.2@840,2098.5 ; v1(930,2040) C32.2@930,2088.5 ; v1(970,3095) 970,3065 C10.1@980,3055 ; v1(1000,2340) 1000,2370 1010,2380 C22.1@1003.3,2386.7 C22.1@1000,2390 ; v1(1005,2770) 1022.73,2787.73 C18.2@1042.27,2787.73 ; C16.2@1021.5,2558.5 1030,2550 1030,2530 1035,2525 v1(1035,2520) ; C14.2@1033.3,3013.3 1070,2976.59 v1(1070,2970) 1070,2960 C21.1@1095,2935 ; v1(1055,2830) 1095,2830 C17.2@1100,2835 ; C17.2@1092.27,2847.73 C17.2@1100,2840 ; C13.2@1160,2443.62 v1(1160,2490) ; R43.1@1180,948.5 R43.1@1186,948.5 1186,903 v1@1190,899 ; R40.1@1200,1613.62 v1(1200,1660) ; v1(1235,5650) C58.2@1266.38,5650 ; v1(1245,5575) 1245,5595 C57.2@1260,5610 ; R41.1@1260,1613.62 v1(1260,1660) ; v1(1280,2815) C20.2@1315,2780 ; v1(1304,676) C42.1@1304,722 ; v1(1335,2835) 1345,2835 C24.1@1360,2850 ; C41.2@1343,1021 C41.2@1344.62,1019.38 ; C41.2@1344,1019.38 C41.2@1344.62,1019.38 ; C56.2@1360,5713.62 1376.38,5713.62 1377,5713 v1(1388,5713) ; C25.1@1378,2780 1383,2785 1384,2784 v1(1419,2784) ; v1(1384,1019) 1382,1019 1381.62,1019.38 C41.2@1344.62,1019.38 ; C55.2@1423.62,5300 v1(1454,5300) ; v1(1435,2665) 1455,2665 C23.1@1475,2645 ; v1(1442,2900) 1455,2900 C11.2@1470,2915 ; v1(1490,3060) 1504,3046 C9.1@1520,3030 ; C12.2@1526.7,2586.7 1543.41,2570 v1(1569,2570) ; C51.2@1570,5800 1570,5820 v1(1580,5830) ; C54.2@1590,5250 1592,5248 v1(1592,5225) ; v1(1600,2370) 1600,2375.34 C39.2@1627.59,2402.93 ; C38.2@1604.84,2262.93 1625,2242.76 v1(1625,2220) ; C61.2@1633.62,5710 v1(1660,5710) ; v1(1660,2235) 1660,2271.22 R35.2@1671.92,2283.15 ; v1(1740,5524) C60.2@1774.38,5524 ; v1(1740,5573) 1773.38,5573 C59.2@1774.38,5574 ; v1(1743,5629) 1776.38,5629 C52.2@1777.38,5630 C52.2@1786.38,5630 ; v1(1745,5300) C53.2@1776.38,5300 ; C66.2@1990,5216.38 2003.62,5230 v1(2025,5230) ; v1(2010,5520) C63.2@2010,5560 ; C62.2@2050,5660 2100,5610 v1(2110,5610) ; R67.1@2080,5373.62 v1(2080,5410) ; v1(2120,5710) J10.9@2155,5710 ; J10.5@2205,5560 v1(2240,5560) ; J10.3@2205,5660 v1(2240,5660)
  Bottom Signal w20: v1(701,3964) R26.1@701,4009
  Bottom Signal w25: R27.1@645,1630 v1(670,1655)
  other v1: 1186,897 190,1050 550,2120 1470,2160 1710,2160 550,2200 1550,2210 1810,2240 1266.38,2242.76 1288,2323 1960,2500 1980,2650 1800,2660 1240,2740 1800,2740 1820,2810 1480,2860 1500,2960 1289,3161 200,3550 540,3780 540,3830 1440,5030 1750,5223 1030,5355 1960,5575 1960,5645 1092,5686
GPIO0: J6.40 U1.79 | length 1471.6
  Top Signal w5: U1.79@1490.33,2779.78 1510.55,2800 1610,2800 1781.1,2628.9 1781.1,1728.9 v1(1790,1720)
  Bottom Signal w5: v1(1790,1720) 1860,1650 J6.40@1950,1650
GPIO1: J6.39 U1.78 | length 1574.8
  Top Signal w5: U1.78@1504.25,2765.86 1527.39,2789 1601,2789 1765.35,2624.65 1765.35,1589.65 v1(1775,1580)
  Bottom Signal w5: v1(1775,1580) 1805,1550 J6.39@1950,1550
GPIO2_BP: J6.36 R71.2 | length 943.5
  Bottom Signal w5: R71.2@1854,1988.5 R71.2@1854,1980.1 1854,1946 2100,1700 2100,1330 2070,1300 2000,1300 J6.36@1950,1250
GPIO2_FSIRXD1: J11.7 R71.1 U1.77 | length 1052.5
  Top Signal w5: U1.77@1518.17,2751.94 1536.23,2770 1598.62,2770 1743,2625.62 v1(1743,2087.9)
  Bottom Signal w5: v1(1743,2087.9) 1779.41,2051.5 1854,2051.5 1855.5,2050 J11.7@1950,2050
GPIO3: J6.35 U1.76 | length 1872.8
  Top Signal w5: U1.76@1520,2725.93 1550.07,2756 1594,2756 1730,2620 1730,2115 1715,2100 1715,1515 1850,1380 1850,1215 v1(1870,1195)
  Bottom Signal w5: v1(1870,1195) 1915,1150 J6.35@1950,1150
GPIO4: J2.36 U1.75 | length 1374.8
  Top Signal w5: U1.75@1532.09,2641.98 1540.11,2650 1580,2650 v1(1610,2680) ; v1(1810,3710) 1810,3730 1830,3750 J2.36@1950,3750
  Bottom Signal w5: v1(1610,2680) 1810,2880 v1(1810,3710)
GPIO5: J2.35 U1.89 | length 1174.4
  Top Signal w5: U1.89@1351.14,2918.97 1390,2957.84 1390,2960 1408.74,2978.74 v1(1408.74,2982.19) ; v1(1590,3615) 1625,3650 J2.35@1950,3650
  Bottom Signal w5: v1(1408.74,2982.19) 1412.19,2982.19 1470,3040 1470,3130 1560,3220 1560,3590 1585,3615 v1(1590,3615)
GPIO6_BP: J6.38 R44.2 | length 752
  Top Signal w5: J6.38@1960,1460 2000,1500 2080,1500 2145,1565 R44.2@2145,2088.5
GPIO6_FSITXD0: J11.6 R44.1 U1.97 | length 1577.4
  Top Signal w5: U1.97@1239.78,3030.33 1279.45,3070 1280,3070 1290,3080 1515,3080 2085,2510 2085,2420 2145,2360 R44.1@2145,2155 ; J11.6@2050,2150 2051.5,2151.5 R44.1@2145,2151.5
GPIO7_BP: J6.37 R45.2 | length 1272.7
  Top Signal w5: J6.37@1960,1360 2000,1400 2120,1400 2180,1460 2180,2355 2116.5,2418.5 R45.2@2116.5,2445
